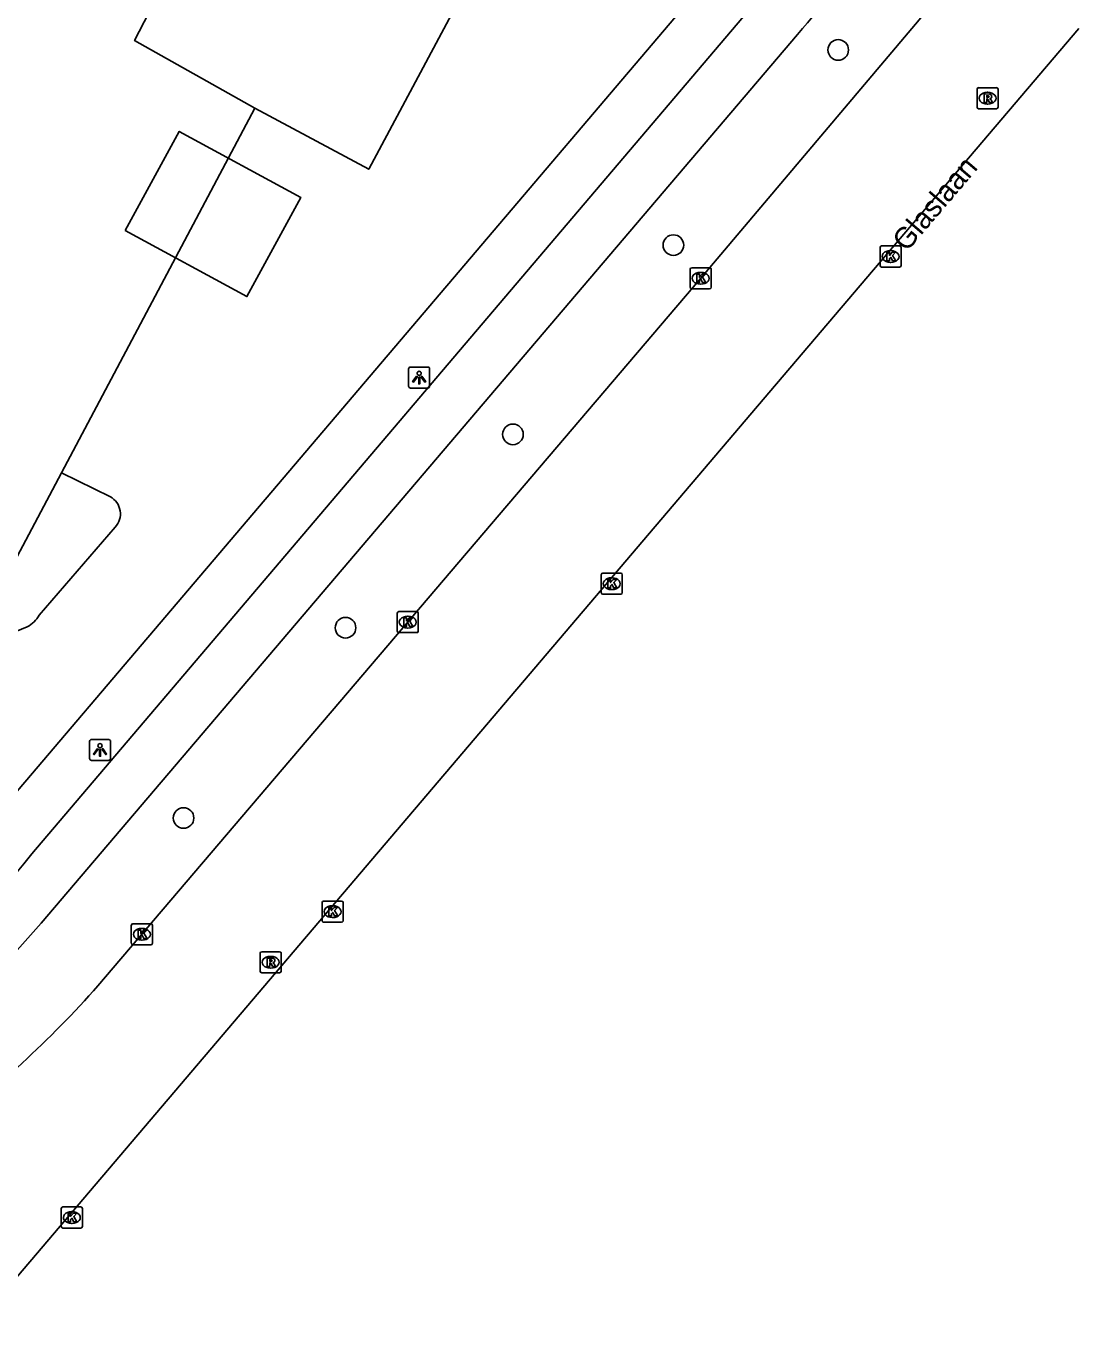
# Model space of a CAD drawing. Extents: x 159489 to 160304, y 383826 to 384530.
# Drawn here: x 160149.6 to 160199.6, y 383845 to 383907.3 of the extents above; entities that cross this region are included whole.
import ezdxf

# ---------------------------------------------------------------- set-up
doc = ezdxf.new("R2010")
doc.units = 0
for name, color, linetype in [('IMGEO_Boom', 7, 'Continuous'), ('IMGEO_Fietspad_gesloten', 7, 'Continuous'), ('IMGEO_Groenvoorziening', 7, 'Continuous'), ('IMGEO_Kolk', 7, 'Continuous'), ('IMGEO_Lichtpunt', 7, 'Continuous'), ('IMGEO_Openbare_ruimte_label', 7, 'Continuous'), ('IMGEO_Pand', 7, 'Continuous'), ('IMGEO_Pand_vergunning_verleend', 7, 'Continuous'), ('IMGEO_Rijbaan_lokaal_gesloten', 7, 'Continuous'), ('IMGEO_Rijbaan_lokaal_open', 7, 'Continuous'), ('IMGEO_Rioolput', 7, 'Continuous')]:
    doc.layers.add(name, color=color, linetype=linetype)

msp = doc.modelspace()

# ---------------------------------------------------------------- linework, layer by layer
at = {"layer": 'IMGEO_Boom'}
for centre in [(160188.162, 383906.178), (160180.339, 383896.918), (160172.725, 383887.938), (160164.781, 383878.762), (160157.095, 383869.735)]:
    msp.add_circle(centre, 0.489, dxfattribs=at)
at = {"layer": 'IMGEO_Fietspad_gesloten'}
for points in [[(160149.897, 383868.032), (160185.469, 383909.903)], [(160150.338, 383864.738), (160186.226, 383906.909)]]:
    msp.add_lwpolyline(points, dxfattribs=at)
for centre, radius, start, end in [((160085.669, 383993.053), 132.41, 319.41434, 324.53403), ((160113.606, 383896.673), 46.232, 297.49985, 321.71949), ((160111.679, 383898.559), 51.365, 298.52791, 318.81939)]:
    msp.add_arc(centre, radius, start, end, dxfattribs=at)
at = {"layer": 'IMGEO_Groenvoorziening'}
msp.add_lwpolyline([(160151.308, 383886.109), (160148.779, 383881.33)], dxfattribs=at)
at = {"layer": 'IMGEO_Kolk'}
for p, q in [((160190.146, 383895.952), (160190.146, 383896.804)), ((160190.221, 383896.878), (160191.073, 383896.878)), ((160190.634, 383896.658), (160190.659, 383896.658)), ((160191.147, 383896.804), (160191.147, 383895.952)), ((160181.133, 383894.917), (160181.133, 383895.769)), ((160181.208, 383895.843), (160182.06, 383895.843)), ((160182.134, 383895.769), (160182.134, 383894.917)), ((160191.073, 383895.878), (160190.221, 383895.878)), ((160190.657, 383896.098), (160190.632, 383896.098)), ((160181.621, 383895.623), (160181.646, 383895.623)), ((160182.06, 383894.843), (160181.208, 383894.843)), ((160181.644, 383895.063), (160181.619, 383895.063)), ((160176.914, 383880.427), (160176.914, 383881.279)), ((160176.989, 383881.353), (160177.841, 383881.353)), ((160177.402, 383881.133), (160177.427, 383881.133)), ((160177.915, 383881.279), (160177.915, 383880.427)), ((160177.841, 383880.353), (160176.989, 383880.353)), ((160177.425, 383880.573), (160177.4, 383880.573)), ((160167.309, 383879.529), (160168.161, 383879.529)), ((160167.234, 383878.603), (160167.234, 383879.455)), ((160167.722, 383879.309), (160167.747, 383879.309)), ((160168.235, 383879.455), (160168.235, 383878.603)), ((160168.161, 383878.529), (160167.309, 383878.529)), ((160167.745, 383878.749), (160167.72, 383878.749)), ((160163.667, 383864.866), (160163.667, 383865.718)), ((160163.742, 383865.792), (160164.594, 383865.792)), ((160164.155, 383865.572), (160164.18, 383865.572)), ((160164.668, 383865.718), (160164.668, 383864.866)), ((160154.616, 383863.791), (160154.616, 383864.643)), ((160154.691, 383864.717), (160155.543, 383864.717)), ((160155.617, 383864.643), (160155.617, 383863.791)), ((160164.594, 383864.792), (160163.742, 383864.792)), ((160164.178, 383865.012), (160164.153, 383865.012)), ((160155.127, 383863.937), (160155.102, 383863.937)), ((160155.104, 383864.497), (160155.129, 383864.497)), ((160155.543, 383863.717), (160154.691, 383863.717)), ((160151.292, 383850.354), (160151.292, 383851.206)), ((160151.367, 383851.28), (160152.219, 383851.28)), ((160151.78, 383851.06), (160151.805, 383851.06)), ((160152.293, 383851.206), (160152.293, 383850.354)), ((160152.219, 383850.28), (160151.367, 383850.28)), ((160151.803, 383850.5), (160151.778, 383850.5))]:
    msp.add_line(p, q, dxfattribs=at)
for points in [[(160190.146, 383895.952), (160190.146, 383896.804)], [(160190.221, 383896.878), (160191.073, 383896.878)], [(160190.467, 383896.578), (160190.59, 383896.578), (160190.59, 383896.427), (160190.72, 383896.578), (160190.884, 383896.578), (160190.738, 383896.427), (160190.891, 383896.178), (160190.739, 383896.178), (160190.654, 383896.342), (160190.59, 383896.275), (160190.59, 383896.178), (160190.467, 383896.178), (160190.467, 383896.578)], [(160191.147, 383896.804), (160191.147, 383895.952)], [(160181.133, 383894.917), (160181.133, 383895.769)], [(160181.208, 383895.843), (160182.06, 383895.843)], [(160182.134, 383895.769), (160182.134, 383894.917)], [(160191.073, 383895.878), (160190.221, 383895.878)], [(160181.454, 383895.543), (160181.577, 383895.543), (160181.577, 383895.392), (160181.707, 383895.543), (160181.871, 383895.543), (160181.725, 383895.392), (160181.878, 383895.143), (160181.726, 383895.143), (160181.641, 383895.307), (160181.577, 383895.24), (160181.577, 383895.143), (160181.454, 383895.143), (160181.454, 383895.543)], [(160182.06, 383894.843), (160181.208, 383894.843)], [(160176.914, 383880.427), (160176.914, 383881.279)], [(160176.989, 383881.353), (160177.841, 383881.353)], [(160177.235, 383881.053), (160177.358, 383881.053), (160177.358, 383880.902), (160177.488, 383881.053), (160177.652, 383881.053), (160177.506, 383880.902), (160177.659, 383880.653), (160177.507, 383880.653), (160177.422, 383880.817), (160177.358, 383880.75), (160177.358, 383880.653), (160177.235, 383880.653), (160177.235, 383881.053)], [(160177.915, 383881.279), (160177.915, 383880.427)], [(160177.841, 383880.353), (160176.989, 383880.353)], [(160167.309, 383879.529), (160168.161, 383879.529)], [(160167.234, 383878.603), (160167.234, 383879.455)], [(160167.555, 383879.229), (160167.678, 383879.229), (160167.678, 383879.078), (160167.808, 383879.229), (160167.972, 383879.229), (160167.826, 383879.078), (160167.979, 383878.829), (160167.827, 383878.829), (160167.742, 383878.993), (160167.678, 383878.926), (160167.678, 383878.829), (160167.555, 383878.829), (160167.555, 383879.229)], [(160168.235, 383879.455), (160168.235, 383878.603)], [(160168.161, 383878.529), (160167.309, 383878.529)], [(160163.667, 383864.866), (160163.667, 383865.718)], [(160163.742, 383865.792), (160164.594, 383865.792)], [(160163.988, 383865.492), (160164.111, 383865.492), (160164.111, 383865.341), (160164.241, 383865.492), (160164.405, 383865.492), (160164.259, 383865.341), (160164.412, 383865.092), (160164.26, 383865.092), (160164.175, 383865.256), (160164.111, 383865.189), (160164.111, 383865.092), (160163.988, 383865.092), (160163.988, 383865.492)], [(160164.668, 383865.718), (160164.668, 383864.866)], [(160154.616, 383863.791), (160154.616, 383864.643)], [(160154.691, 383864.717), (160155.543, 383864.717)], [(160155.617, 383864.643), (160155.617, 383863.791)], [(160164.594, 383864.792), (160163.742, 383864.792)], [(160154.937, 383864.417), (160155.06, 383864.417), (160155.06, 383864.266), (160155.19, 383864.417), (160155.354, 383864.417), (160155.208, 383864.266), (160155.361, 383864.017), (160155.209, 383864.017), (160155.124, 383864.181), (160155.06, 383864.114), (160155.06, 383864.017), (160154.937, 383864.017), (160154.937, 383864.417)], [(160155.543, 383863.717), (160154.691, 383863.717)], [(160151.292, 383850.354), (160151.292, 383851.206)], [(160151.367, 383851.28), (160152.219, 383851.28)], [(160151.613, 383850.98), (160151.736, 383850.98), (160151.736, 383850.829), (160151.866, 383850.98), (160152.03, 383850.98), (160151.884, 383850.829), (160152.037, 383850.58), (160151.885, 383850.58), (160151.8, 383850.744), (160151.736, 383850.677), (160151.736, 383850.58), (160151.613, 383850.58), (160151.613, 383850.98)], [(160152.293, 383851.206), (160152.293, 383850.354)], [(160152.219, 383850.28), (160151.367, 383850.28)]]:
    msp.add_lwpolyline(points, dxfattribs=at)
for centre, start, end in [((160190.223, 383896.802), 91.55205, 178.44795), ((160190.223, 383896.802), 91.55205, 178.44795), ((160191.071, 383896.802), 1.55205, 88.44795), ((160191.071, 383896.802), 1.55205, 88.44795), ((160181.21, 383895.767), 91.55205, 178.44795), ((160181.21, 383895.767), 91.55205, 178.44795), ((160182.058, 383895.767), 1.55205, 88.44795), ((160182.058, 383895.767), 1.55205, 88.44795), ((160190.223, 383895.954), 181.55205, 268.44795), ((160190.223, 383895.954), 181.55205, 268.44795), ((160191.071, 383895.954), 271.55205, 358.44795), ((160191.071, 383895.954), 271.55205, 358.44795), ((160181.21, 383894.919), 181.55205, 268.44795), ((160181.21, 383894.919), 181.55205, 268.44795), ((160182.058, 383894.919), 271.55205, 358.44795), ((160182.058, 383894.919), 271.55205, 358.44795), ((160176.991, 383881.277), 91.55205, 178.44795), ((160176.991, 383881.277), 91.55205, 178.44795), ((160177.839, 383881.277), 1.55205, 88.44795), ((160177.839, 383881.277), 1.55205, 88.44795), ((160176.991, 383880.429), 181.55205, 268.44795), ((160176.991, 383880.429), 181.55205, 268.44795), ((160177.839, 383880.429), 271.55205, 358.44795), ((160177.839, 383880.429), 271.55205, 358.44795), ((160167.311, 383879.453), 91.55205, 178.44795), ((160167.311, 383879.453), 91.55205, 178.44795), ((160168.159, 383879.453), 1.55205, 88.44795), ((160168.159, 383879.453), 1.55205, 88.44795), ((160167.311, 383878.605), 181.55205, 268.44795), ((160167.311, 383878.605), 181.55205, 268.44795), ((160168.159, 383878.605), 271.55205, 358.44795), ((160168.159, 383878.605), 271.55205, 358.44795), ((160163.744, 383865.716), 91.55205, 178.44795), ((160163.744, 383865.716), 91.55205, 178.44795), ((160164.592, 383865.716), 1.55205, 88.44795), ((160164.592, 383865.716), 1.55205, 88.44795), ((160154.693, 383864.641), 91.55205, 178.44795), ((160154.693, 383864.641), 91.55205, 178.44795), ((160155.541, 383864.641), 1.55205, 88.44795), ((160155.541, 383864.641), 1.55205, 88.44795), ((160163.744, 383864.868), 181.55205, 268.44795), ((160163.744, 383864.868), 181.55205, 268.44795), ((160164.592, 383864.868), 271.55205, 358.44795), ((160164.592, 383864.868), 271.55205, 358.44795), ((160154.693, 383863.793), 181.55205, 268.44795), ((160154.693, 383863.793), 181.55205, 268.44795), ((160155.541, 383863.793), 271.55205, 358.44795), ((160155.541, 383863.793), 271.55205, 358.44795), ((160151.369, 383851.204), 91.55205, 178.44795), ((160151.369, 383851.204), 91.55205, 178.44795), ((160152.217, 383851.204), 1.55205, 88.44795), ((160152.217, 383851.204), 1.55205, 88.44795), ((160151.369, 383850.356), 181.55205, 268.44795), ((160151.369, 383850.356), 181.55205, 268.44795), ((160152.217, 383850.356), 271.55205, 358.44795), ((160152.217, 383850.356), 271.55205, 358.44795)]:
    msp.add_arc(centre, 0.0765, start, end, dxfattribs=at)
for centre, major_axis, ratio, start_param, end_param in [((160190.633, 383896.378), (-0.387, 0.002), 0.722429, 4.712389, 7.853982), ((160190.658, 383896.378), (-0.39, 0.002), 0.717154, 1.570796, 4.712389), ((160181.62, 383895.343), (-0.387, 0.002), 0.722429, 4.712389, 7.853982), ((160181.645, 383895.343), (-0.39, 0.002), 0.717154, 1.570796, 4.712389), ((160177.401, 383880.853), (-0.387, 0.002), 0.722429, 4.712389, 7.853982), ((160177.426, 383880.853), (-0.39, 0.002), 0.717154, 1.570796, 4.712389), ((160167.721, 383879.029), (-0.387, 0.002), 0.722429, 4.712389, 7.853982), ((160167.746, 383879.029), (-0.39, 0.002), 0.717154, 1.570796, 4.712389), ((160164.154, 383865.292), (-0.387, 0.002), 0.722429, 4.712389, 7.853982), ((160164.179, 383865.292), (-0.39, 0.002), 0.717154, 1.570796, 4.712389), ((160155.103, 383864.217), (-0.387, 0.002), 0.722429, 4.712389, 7.853982), ((160155.128, 383864.217), (-0.39, 0.002), 0.717154, 1.570796, 4.712389), ((160151.779, 383850.78), (-0.387, 0.002), 0.722429, 4.712389, 7.853982), ((160151.804, 383850.78), (-0.39, 0.002), 0.717154, 1.570796, 4.712389)]:
    msp.add_ellipse(centre, major_axis=major_axis, ratio=ratio, start_param=start_param, end_param=end_param, dxfattribs=at)
at = {"layer": 'IMGEO_Lichtpunt'}
for p, q in [((160167.776, 383891.038), (160167.776, 383890.231)), ((160167.776, 383891.038), (160167.776, 383890.231)), ((160168.678, 383891.133), (160167.87, 383891.133)), ((160168.678, 383891.133), (160167.87, 383891.133)), ((160168.772, 383890.231), (160168.772, 383891.038)), ((160168.772, 383890.231), (160168.772, 383891.038)), ((160167.87, 383890.137), (160168.678, 383890.137)), ((160167.87, 383890.137), (160168.678, 383890.137)), ((160152.633, 383873.369), (160152.633, 383872.562)), ((160152.633, 383873.369), (160152.633, 383872.562)), ((160153.535, 383873.464), (160152.727, 383873.464)), ((160153.535, 383873.464), (160152.727, 383873.464)), ((160153.629, 383872.562), (160153.629, 383873.369)), ((160153.629, 383872.562), (160153.629, 383873.369)), ((160152.727, 383872.468), (160153.535, 383872.468)), ((160152.727, 383872.468), (160153.535, 383872.468))]:
    msp.add_line(p, q, dxfattribs=at)
for points in [[(160168.15, 383890.702), (160168.189, 383890.674), (160168.001, 383890.412), (160167.963, 383890.439), (160168.15, 383890.702)], [(160168.252, 383890.654), (160168.299, 383890.654), (160168.299, 383890.332), (160168.252, 383890.332), (160168.252, 383890.654)], [(160168.362, 383890.674), (160168.4, 383890.701), (160168.587, 383890.439), (160168.548, 383890.411), (160168.362, 383890.674)], [(160153.007, 383873.033), (160153.046, 383873.005), (160152.858, 383872.743), (160152.82, 383872.77), (160153.007, 383873.033)], [(160153.109, 383872.985), (160153.156, 383872.985), (160153.156, 383872.663), (160153.109, 383872.663), (160153.109, 383872.985)], [(160153.219, 383873.005), (160153.257, 383873.032), (160153.444, 383872.77), (160153.405, 383872.742), (160153.219, 383873.005)]]:
    msp.add_lwpolyline(points, dxfattribs=at)
for centre in [(160168.275, 383890.836), (160153.132, 383873.167)]:
    msp.add_circle(centre, 0.0994, dxfattribs=at)
for centre, start, end in [((160167.87, 383891.038), 90, 180), ((160167.87, 383891.038), 90, 180), ((160168.678, 383891.038), 0, 90), ((160168.678, 383891.038), 0, 90), ((160167.87, 383890.231), 180, 270), ((160167.87, 383890.231), 180, 270), ((160168.678, 383890.231), 270, 0), ((160168.678, 383890.231), 270, 360), ((160152.727, 383873.369), 90, 180), ((160152.727, 383873.369), 90, 180), ((160153.535, 383873.369), 0, 90), ((160153.535, 383873.369), 0, 90), ((160152.727, 383872.562), 180, 270), ((160152.727, 383872.562), 180, 270), ((160153.535, 383872.562), 270, 0), ((160153.535, 383872.562), 270, 360)]:
    msp.add_arc(centre, 0.0946, start, end, dxfattribs=at)
at = {"layer": 'IMGEO_Pand'}
for points in [[(160182.489, 383918.88), (160177.2, 383921.7), (160165.88, 383900.52), (160160.47, 383903.419)], [(160146.426, 383916.245), (160156.806, 383910.583), (160154.77, 383906.62), (160160.47, 383903.419)]]:
    msp.add_lwpolyline(points, dxfattribs=at)
at = {"layer": 'IMGEO_Pand_vergunning_verleend'}
msp.add_lwpolyline([(160154.33, 383897.617), (160156.888, 383902.315), (160162.661, 383899.171), (160160.103, 383894.473), (160154.33, 383897.617)], dxfattribs=at)
at = {"layer": 'IMGEO_Rijbaan_lokaal_gesloten'}
for points in [[(160193.375, 383909.247), (160181.634, 383895.343), (160153.034, 383861.772)], [(160146.634, 383844.98), (160184.33, 383889.277), (160199.575, 383907.191)]]:
    msp.add_lwpolyline(points, dxfattribs=at)
msp.add_arc((160114.151, 383896.301), 52.001, 307.0546, 318.39381, dxfattribs=at)
at = {"layer": 'IMGEO_Rijbaan_lokaal_open'}
for points in [[(160146.393, 383867.768), (160146.756, 383868.165), (160180.989, 383908.397)], [(160160.47, 383903.419), (160151.308, 383886.109)], [(160151.308, 383886.109), (160153.62, 383884.978)], [(160153.853, 383883.534), (160150.247, 383879.36)], [(160149.675, 383878.803), (160146.922, 383877.677)]]:
    msp.add_lwpolyline(points, dxfattribs=at)
for centre, radius, start, end in [((160153.163, 383884.163), 0.934, 317.63881, 60.69337), ((160148.924, 383880.146), 1.539, 299.20375, 329.27387)]:
    msp.add_arc(centre, radius, start, end, dxfattribs=at)
at = {"layer": 'IMGEO_Rioolput'}
for p, q in [((160194.748, 383903.462), (160194.748, 383904.314)), ((160194.823, 383904.388), (160195.675, 383904.388)), ((160195.236, 383904.168), (160195.261, 383904.168)), ((160195.749, 383904.314), (160195.749, 383903.462)), ((160195.675, 383903.388), (160194.823, 383903.388)), ((160195.259, 383903.608), (160195.234, 383903.608)), ((160160.727, 383862.465), (160160.727, 383863.317)), ((160160.802, 383863.391), (160161.654, 383863.391)), ((160161.728, 383863.317), (160161.728, 383862.465)), ((160161.215, 383863.171), (160161.24, 383863.171)), ((160161.654, 383862.391), (160160.802, 383862.391)), ((160161.238, 383862.611), (160161.213, 383862.611))]:
    msp.add_line(p, q, dxfattribs=at)
for points in [[(160194.748, 383903.462), (160194.748, 383904.314)], [(160194.823, 383904.388), (160195.675, 383904.388)], [(160195.337, 383904.086), (160195.085, 383904.088), (160195.085, 383903.688)], [(160195.085, 383903.688), (160195.209, 383903.688), (160195.209, 383903.85), (160195.22, 383903.85)], [(160195.263, 383904.007), (160195.209, 383904.007), (160195.209, 383903.926)], [(160195.209, 383903.926), (160195.261, 383903.926)], [(160195.267, 383903.821), (160195.338, 383903.688), (160195.478, 383903.688), (160195.413, 383903.814)], [(160195.749, 383904.314), (160195.749, 383903.462)], [(160195.675, 383903.388), (160194.823, 383903.388)], [(160160.727, 383862.465), (160160.727, 383863.317)], [(160160.802, 383863.391), (160161.654, 383863.391)], [(160161.728, 383863.317), (160161.728, 383862.465)], [(160161.316, 383863.089), (160161.064, 383863.091), (160161.064, 383862.691)], [(160161.064, 383862.691), (160161.188, 383862.691), (160161.188, 383862.853), (160161.199, 383862.853)], [(160161.242, 383863.01), (160161.188, 383863.01), (160161.188, 383862.929)], [(160161.188, 383862.929), (160161.24, 383862.929)], [(160161.246, 383862.824), (160161.317, 383862.691), (160161.457, 383862.691), (160161.392, 383862.817)], [(160161.654, 383862.391), (160160.802, 383862.391)]]:
    msp.add_lwpolyline(points, dxfattribs=at)
for centre, radius, start, end in [((160194.825, 383904.312), 0.0765, 91.55205, 178.44795), ((160194.825, 383904.312), 0.0765, 91.55205, 178.44795), ((160195.219, 383903.797), 0.0533, 26.02933, 88.69889), ((160195.245, 383904.115), 0.19, 274.7715, 282.96867), ((160195.269, 383903.911), 0.0964, 77.00612, 93.18647), ((160195.283, 383903.968), 0.0378, 276.66336, 79.67722), ((160195.336, 383903.976), 0.109, 350.36119, 89.41601), ((160195.334, 383903.976), 0.112, 277.58423, 350.98172), ((160195.318, 383903.761), 0.108, 29.51342, 73.79051), ((160195.673, 383904.312), 0.0765, 1.55205, 88.44795), ((160195.673, 383904.312), 0.0765, 1.55205, 88.44795), ((160194.825, 383903.464), 0.0765, 181.55205, 268.44795), ((160194.825, 383903.464), 0.0765, 181.55205, 268.44795), ((160195.673, 383903.464), 0.0765, 271.55205, 358.44795), ((160195.673, 383903.464), 0.0765, 271.55205, 358.44795), ((160160.804, 383863.315), 0.0765, 91.55205, 178.44795), ((160160.804, 383863.315), 0.0765, 91.55205, 178.44795), ((160161.652, 383863.315), 0.0765, 1.55205, 88.44795), ((160161.652, 383863.315), 0.0765, 1.55205, 88.44795), ((160161.198, 383862.8), 0.0533, 26.02933, 88.69889), ((160161.224, 383863.118), 0.19, 274.7715, 282.96867), ((160161.248, 383862.914), 0.0964, 77.00612, 93.18647), ((160161.262, 383862.971), 0.0378, 276.66336, 79.67722), ((160161.315, 383862.979), 0.109, 350.36119, 89.41601), ((160161.313, 383862.979), 0.112, 277.58423, 350.98172), ((160161.297, 383862.764), 0.108, 29.51342, 73.79051), ((160160.804, 383862.467), 0.0765, 181.55205, 268.44795), ((160160.804, 383862.467), 0.0765, 181.55205, 268.44795), ((160161.652, 383862.467), 0.0765, 271.55205, 358.44795), ((160161.652, 383862.467), 0.0765, 271.55205, 358.44795)]:
    msp.add_arc(centre, radius, start, end, dxfattribs=at)
for centre, major_axis, ratio, start_param, end_param in [((160195.235, 383903.888), (-0.387, 0.002), 0.722429, 4.712389, 7.853982), ((160195.26, 383903.888), (-0.39, 0.002), 0.717154, 1.570796, 4.712389), ((160161.214, 383862.891), (-0.387, 0.002), 0.722429, 4.712389, 7.853982), ((160161.239, 383862.891), (-0.39, 0.002), 0.717154, 1.570796, 4.712389)]:
    msp.add_ellipse(centre, major_axis=major_axis, ratio=ratio, start_param=start_param, end_param=end_param, dxfattribs=at)

# ---------------------------------------------------------------- texts
at = {"layer": 'IMGEO_Openbare_ruimte_label'}
msp.add_text('Glaslaan', height=1, rotation=49.54162, dxfattribs=at).set_placement((160191.407, 383896.563))

doc.saveas('drawing.dxf')
